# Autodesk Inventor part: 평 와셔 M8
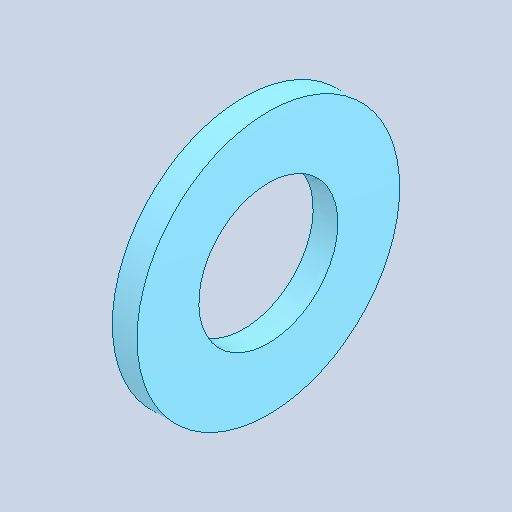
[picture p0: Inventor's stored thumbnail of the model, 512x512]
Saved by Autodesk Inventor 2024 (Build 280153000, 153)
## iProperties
Created: 2025-10
Part Number: 평 와셔 M8
Material: 강철, 연강
Description: 평면 와셔
Document SubType Name: Modeling
Designer: EDU03
Density: 7.85 g/cm^3
Appearance: 기본값
Author: jhkim
Sending System: Autodesk Inventor 2026
Preprocessor: ST-DEVELOPER v20.1
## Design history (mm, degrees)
feature "Solid1"
node "솔리드1"
